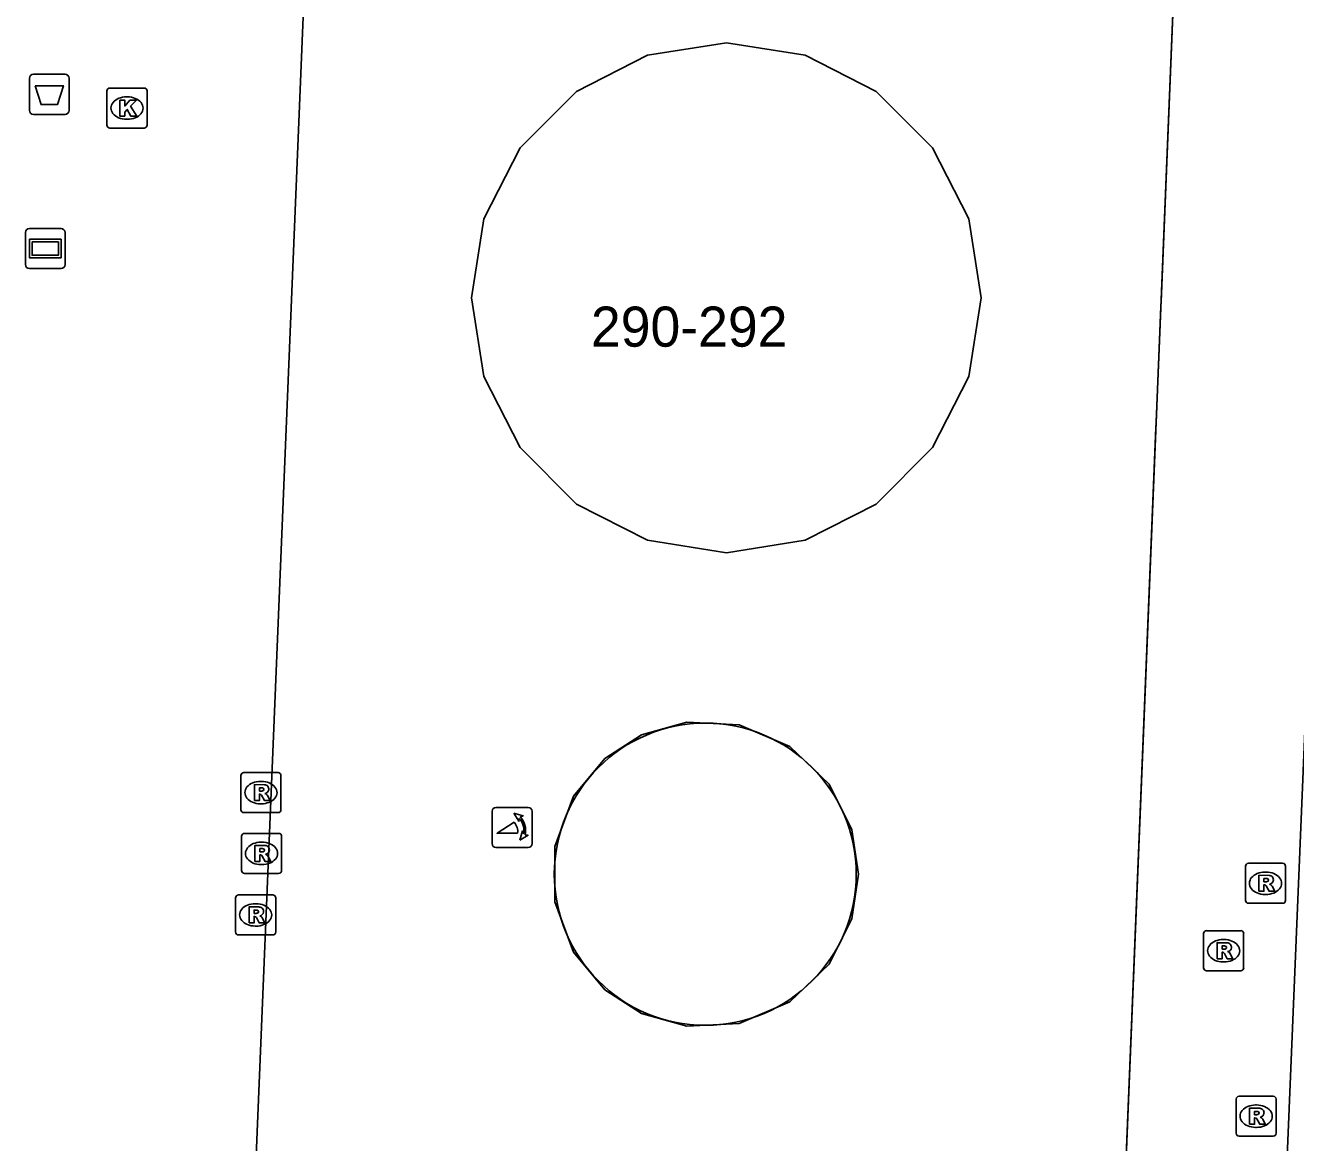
# Model space of a CAD drawing. Extents: x 160891 to 161384, y 386490 to 386907.
# Drawn here: x 161238.26 to 161269.97, y 386705.95 to 386733.83 of the extents above; entities that cross this region are included whole.
import ezdxf

# ---------------------------------------------------------------- set-up
doc = ezdxf.new("R2010")
doc.units = 0
for name, color, linetype in [('IMGEO_Afvalbak', 7, 'Continuous'), ('IMGEO_Kolk', 7, 'Continuous'), ('IMGEO_Pand', 7, 'Continuous'), ('IMGEO_Pand_nummerreeks', 7, 'Continuous'), ('IMGEO_Pand_overbouw', 7, 'Continuous'), ('IMGEO_Poller', 7, 'Continuous'), ('IMGEO_Reclamebord', 7, 'Continuous'), ('IMGEO_Rioolput', 7, 'Continuous'), ('IMGEO_Voetpad_open', 7, 'Continuous')]:
    doc.layers.add(name, color=color, linetype=linetype)

msp = doc.modelspace()

# ---------------------------------------------------------------- linework, layer by layer
at = {"layer": 'IMGEO_Afvalbak'}
for p, q in [((161238.358, 386731.708), (161238.358, 386732.508)), ((161238.358, 386732.508), (161238.358, 386731.708)), ((161238.458, 386732.608), (161239.248, 386732.608)), ((161239.248, 386732.608), (161238.458, 386732.608)), ((161239.348, 386732.508), (161239.348, 386731.708)), ((161239.348, 386731.708), (161239.348, 386732.508)), ((161239.248, 386731.608), (161238.458, 386731.608)), ((161238.458, 386731.608), (161239.248, 386731.608))]:
    msp.add_line(p, q, dxfattribs=at)
msp.add_lwpolyline([(161238.501, 386732.322), (161239.205, 386732.322), (161239.056, 386731.852), (161238.65, 386731.852), (161238.501, 386732.322)], dxfattribs=at)
for centre, start, end in [((161238.458, 386732.508), 90, 180), ((161238.458, 386732.508), 90, 180), ((161239.248, 386732.508), 0, 90), ((161239.248, 386732.508), 360, 90), ((161238.458, 386731.708), 180, 270), ((161238.458, 386731.708), 180, 270), ((161239.248, 386731.708), 270, 0), ((161239.248, 386731.708), 270, 0)]:
    msp.add_arc(centre, 0.1, start, end, dxfattribs=at)
at = {"layer": 'IMGEO_Kolk'}
for p, q in [((161240.293, 386731.339), (161240.293, 386732.191)), ((161240.368, 386732.265), (161241.22, 386732.265)), ((161241.294, 386732.191), (161241.294, 386731.339)), ((161240.781, 386732.045), (161240.806, 386732.045)), ((161241.22, 386731.265), (161240.368, 386731.265)), ((161240.804, 386731.485), (161240.779, 386731.485))]:
    msp.add_line(p, q, dxfattribs=at)
for points in [[(161240.293, 386731.339), (161240.293, 386732.191)], [(161240.368, 386732.265), (161241.22, 386732.265)], [(161241.294, 386732.191), (161241.294, 386731.339)], [(161240.614, 386731.965), (161240.737, 386731.965), (161240.737, 386731.814), (161240.867, 386731.965), (161241.031, 386731.965), (161240.885, 386731.814), (161241.038, 386731.565), (161240.886, 386731.565), (161240.801, 386731.729), (161240.737, 386731.662), (161240.737, 386731.565), (161240.614, 386731.565), (161240.614, 386731.965)], [(161241.22, 386731.265), (161240.368, 386731.265)]]:
    msp.add_lwpolyline(points, dxfattribs=at)
for centre, start, end in [((161240.37, 386732.189), 91.552, 178.448), ((161240.37, 386732.189), 91.552, 178.448), ((161241.218, 386732.189), 1.552, 88.448), ((161241.218, 386732.189), 1.552, 88.448), ((161240.37, 386731.341), 181.552, 268.448), ((161240.37, 386731.341), 181.552, 268.448), ((161241.218, 386731.341), 271.552, 358.448), ((161241.218, 386731.341), 271.552, 358.448)]:
    msp.add_arc(centre, 0.0765, start, end, dxfattribs=at)
for centre, major_axis, ratio, start_param, end_param in [((161240.78, 386731.765), (-0.387, 0.002), 0.722429, 4.712389, 7.853982), ((161240.805, 386731.765), (-0.39, 0.002), 0.717154, 1.570796, 4.712389)]:
    msp.add_ellipse(centre, major_axis=major_axis, ratio=ratio, start_param=start_param, end_param=end_param, dxfattribs=at)
at = {"layer": 'IMGEO_Pand'}
msp.add_lwpolyline([(161257.725, 386720.977), (161259.499, 386721.882), (161260.908, 386723.29), (161261.812, 386725.064), (161262.123, 386727.031), (161261.812, 386728.998), (161260.908, 386730.772), (161259.499, 386732.18), (161257.725, 386733.084), (161255.758, 386733.396), (161253.791, 386733.084), (161252.017, 386732.18), (161250.609, 386730.772), (161249.705, 386728.998), (161249.393, 386727.031), (161249.705, 386725.064), (161250.609, 386723.29), (161252.017, 386721.882), (161253.791, 386720.977), (161255.758, 386720.666), (161257.725, 386720.977)], dxfattribs=at)
at = {"layer": 'IMGEO_Pand_overbouw'}
for points in [[(161267.088, 386738.621), (161245.413, 386739.487), (161243.237, 386686.658), (161264.93, 386685.782)], [(161257.725, 386720.977), (161255.758, 386720.666), (161253.791, 386720.977), (161252.017, 386721.882), (161250.609, 386723.29), (161249.705, 386725.064), (161249.393, 386727.031), (161249.705, 386728.998), (161250.609, 386730.772), (161252.017, 386732.18), (161253.791, 386733.084), (161255.758, 386733.396), (161257.725, 386733.084), (161259.499, 386732.18), (161260.908, 386730.772), (161261.812, 386728.998), (161262.123, 386727.031), (161261.812, 386725.064), (161260.908, 386723.29), (161259.499, 386721.882)], [(161259.055, 386712.644), (161258.89, 386711.533), (161258.325, 386710.398), (161257.341, 386709.456), (161256.074, 386708.915), (161254.769, 386708.85), (161253.639, 386709.169), (161252.725, 386709.759), (161251.942, 386710.698), (161251.473, 386711.952), (161251.473, 386713.335), (161251.942, 386714.589), (161252.725, 386715.529), (161253.639, 386716.118), (161254.769, 386716.438), (161256.074, 386716.372), (161257.341, 386715.832), (161258.325, 386714.889), (161258.89, 386713.754)]]:
    msp.add_lwpolyline(points, close=True, dxfattribs=at)
at = {"layer": 'IMGEO_Poller'}
for p, q in [((161249.91, 386714.213), (161249.91, 386713.406)), ((161249.91, 386714.213), (161249.91, 386713.406)), ((161250.812, 386714.308), (161250.004, 386714.308)), ((161250.812, 386714.308), (161250.004, 386714.308)), ((161250.906, 386713.406), (161250.906, 386714.213)), ((161250.906, 386713.406), (161250.906, 386714.213)), ((161250.004, 386713.311), (161250.812, 386713.311)), ((161250.004, 386713.311), (161250.812, 386713.311))]:
    msp.add_line(p, q, dxfattribs=at)
for points in [[(161250.589, 386714.037), (161250.577, 386713.964), (161250.452, 386714.169)], [(161250.452, 386714.169), (161250.683, 386714.103), (161250.612, 386714.071)], [(161250.545, 386713.664), (161250.032, 386713.664), (161250.462, 386713.939)], [(161250.605, 386713.492), (161250.671, 386713.723), (161250.701, 386713.655)], [(161250.737, 386713.628), (161250.809, 386713.617), (161250.605, 386713.492)]]:
    msp.add_lwpolyline(points, dxfattribs=at)
for centre, radius, start, end in [((161250.004, 386714.213), 0.0946, 90, 180), ((161250.004, 386714.213), 0.0946, 90, 180), ((161250.812, 386714.213), 0.0946, 0, 90), ((161250.812, 386714.213), 0.0946, 0, 90), ((161250.217, 386713.714), 0.332, 351.3247, 42.4854), ((161250.231, 386713.724), 0.476, 351.7527, 41.1691), ((161250.231, 386713.724), 0.516, 349.3569, 42.2912), ((161250.004, 386713.406), 0.0946, 180, 270), ((161250.004, 386713.406), 0.0946, 180, 270), ((161250.812, 386713.406), 0.0946, 270, 0), ((161250.812, 386713.406), 0.0946, 270, 0)]:
    msp.add_arc(centre, radius, start, end, dxfattribs=at)
at = {"layer": 'IMGEO_Reclamebord'}
for p, q in [((161238.357, 386728.759), (161239.147, 386728.759)), ((161239.147, 386728.759), (161238.357, 386728.759)), ((161238.257, 386727.859), (161238.257, 386728.659)), ((161238.257, 386728.659), (161238.257, 386727.859)), ((161239.247, 386728.659), (161239.247, 386727.859)), ((161239.247, 386727.859), (161239.247, 386728.659)), ((161239.147, 386727.759), (161238.357, 386727.759)), ((161238.357, 386727.759), (161239.147, 386727.759))]:
    msp.add_line(p, q, dxfattribs=at)
for points in [[(161238.358, 386728.491), (161239.146, 386728.491), (161239.146, 386728.027), (161238.358, 386728.027), (161238.358, 386728.491)], [(161238.423, 386728.426), (161238.423, 386728.092), (161239.081, 386728.092), (161239.081, 386728.426), (161238.423, 386728.426)]]:
    msp.add_lwpolyline(points, dxfattribs=at)
for centre, start, end in [((161238.357, 386728.659), 90, 180), ((161238.357, 386728.659), 90, 180), ((161239.147, 386728.659), 0, 90), ((161239.147, 386728.659), 360, 90), ((161238.357, 386727.859), 180, 270), ((161238.357, 386727.859), 180, 270), ((161239.147, 386727.859), 270, 0), ((161239.147, 386727.859), 270, 0)]:
    msp.add_arc(centre, 0.1, start, end, dxfattribs=at)
at = {"layer": 'IMGEO_Rioolput'}
for p, q in [((161243.637, 386714.254), (161243.637, 386715.106)), ((161243.712, 386715.18), (161244.564, 386715.18)), ((161244.638, 386715.106), (161244.638, 386714.254)), ((161244.125, 386714.96), (161244.15, 386714.96)), ((161244.564, 386714.18), (161243.712, 386714.18)), ((161244.148, 386714.4), (161244.123, 386714.4)), ((161243.652, 386712.737), (161243.652, 386713.589)), ((161243.727, 386713.663), (161244.579, 386713.663)), ((161244.653, 386713.589), (161244.653, 386712.737)), ((161244.14, 386713.443), (161244.165, 386713.443)), ((161244.163, 386712.883), (161244.138, 386712.883)), ((161268.719, 386711.991), (161268.719, 386712.843)), ((161268.794, 386712.917), (161269.646, 386712.917)), ((161269.72, 386712.843), (161269.72, 386711.991)), ((161244.579, 386712.663), (161243.727, 386712.663)), ((161269.207, 386712.697), (161269.232, 386712.697)), ((161243.506, 386711.202), (161243.506, 386712.054)), ((161243.581, 386712.128), (161244.433, 386712.128)), ((161243.994, 386711.908), (161244.019, 386711.908)), ((161244.507, 386712.054), (161244.507, 386711.202)), ((161269.646, 386711.917), (161268.794, 386711.917)), ((161269.23, 386712.137), (161269.205, 386712.137)), ((161244.017, 386711.348), (161243.992, 386711.348)), ((161244.433, 386711.128), (161243.581, 386711.128)), ((161267.673, 386710.308), (161267.673, 386711.16)), ((161267.748, 386711.234), (161268.6, 386711.234)), ((161268.161, 386711.014), (161268.186, 386711.014)), ((161268.674, 386711.16), (161268.674, 386710.308)), ((161268.184, 386710.454), (161268.159, 386710.454)), ((161268.6, 386710.234), (161267.748, 386710.234)), ((161268.485, 386706.178), (161268.485, 386707.03)), ((161268.56, 386707.104), (161269.412, 386707.104)), ((161268.973, 386706.884), (161268.998, 386706.884)), ((161269.486, 386707.03), (161269.486, 386706.178)), ((161268.996, 386706.324), (161268.971, 386706.324)), ((161269.412, 386706.104), (161268.56, 386706.104))]:
    msp.add_line(p, q, dxfattribs=at)
for points in [[(161243.637, 386714.254), (161243.637, 386715.106)], [(161243.712, 386715.18), (161244.564, 386715.18)], [(161244.638, 386715.106), (161244.638, 386714.254)], [(161244.226, 386714.878), (161243.974, 386714.88), (161243.974, 386714.48)], [(161244.152, 386714.799), (161244.098, 386714.799), (161244.098, 386714.718)], [(161243.974, 386714.48), (161244.098, 386714.48), (161244.098, 386714.642), (161244.109, 386714.642)], [(161244.098, 386714.718), (161244.15, 386714.718)], [(161244.156, 386714.613), (161244.227, 386714.48), (161244.367, 386714.48), (161244.302, 386714.606)], [(161244.564, 386714.18), (161243.712, 386714.18)], [(161243.652, 386712.737), (161243.652, 386713.589)], [(161243.727, 386713.663), (161244.579, 386713.663)], [(161244.653, 386713.589), (161244.653, 386712.737)], [(161244.241, 386713.361), (161243.989, 386713.363), (161243.989, 386712.963)], [(161244.167, 386713.282), (161244.113, 386713.282), (161244.113, 386713.201)], [(161244.113, 386713.201), (161244.165, 386713.201)], [(161243.989, 386712.963), (161244.113, 386712.963), (161244.113, 386713.125), (161244.124, 386713.125)], [(161244.171, 386713.096), (161244.242, 386712.963), (161244.382, 386712.963), (161244.317, 386713.089)], [(161268.719, 386711.991), (161268.719, 386712.843)], [(161268.794, 386712.917), (161269.646, 386712.917)], [(161269.72, 386712.843), (161269.72, 386711.991)], [(161244.579, 386712.663), (161243.727, 386712.663)], [(161269.308, 386712.615), (161269.056, 386712.617), (161269.056, 386712.217)], [(161269.234, 386712.536), (161269.18, 386712.536), (161269.18, 386712.455)], [(161269.056, 386712.217), (161269.18, 386712.217), (161269.18, 386712.379), (161269.191, 386712.379)], [(161269.18, 386712.455), (161269.232, 386712.455)], [(161269.238, 386712.35), (161269.309, 386712.217), (161269.449, 386712.217), (161269.384, 386712.343)], [(161243.506, 386711.202), (161243.506, 386712.054)], [(161243.581, 386712.128), (161244.433, 386712.128)], [(161244.507, 386712.054), (161244.507, 386711.202)], [(161269.646, 386711.917), (161268.794, 386711.917)], [(161244.095, 386711.826), (161243.843, 386711.828), (161243.843, 386711.428)], [(161243.843, 386711.428), (161243.967, 386711.428), (161243.967, 386711.59), (161243.978, 386711.59)], [(161244.021, 386711.747), (161243.967, 386711.747), (161243.967, 386711.666)], [(161243.967, 386711.666), (161244.019, 386711.666)], [(161244.025, 386711.561), (161244.096, 386711.428), (161244.236, 386711.428), (161244.171, 386711.554)], [(161244.433, 386711.128), (161243.581, 386711.128)], [(161267.673, 386710.308), (161267.673, 386711.16)], [(161267.748, 386711.234), (161268.6, 386711.234)], [(161268.262, 386710.932), (161268.01, 386710.934), (161268.01, 386710.534)], [(161268.674, 386711.16), (161268.674, 386710.308)], [(161268.01, 386710.534), (161268.134, 386710.534), (161268.134, 386710.696), (161268.145, 386710.696)], [(161268.188, 386710.853), (161268.134, 386710.853), (161268.134, 386710.772)], [(161268.134, 386710.772), (161268.186, 386710.772)], [(161268.192, 386710.667), (161268.263, 386710.534), (161268.403, 386710.534), (161268.338, 386710.66)], [(161268.6, 386710.234), (161267.748, 386710.234)], [(161268.485, 386706.178), (161268.485, 386707.03)], [(161268.56, 386707.104), (161269.412, 386707.104)], [(161269.486, 386707.03), (161269.486, 386706.178)], [(161269.074, 386706.802), (161268.822, 386706.804), (161268.822, 386706.404)], [(161268.822, 386706.404), (161268.946, 386706.404), (161268.946, 386706.566), (161268.957, 386706.566)], [(161269, 386706.723), (161268.946, 386706.723), (161268.946, 386706.642)], [(161268.946, 386706.642), (161268.998, 386706.642)], [(161269.004, 386706.537), (161269.075, 386706.404), (161269.215, 386706.404), (161269.15, 386706.53)], [(161269.412, 386706.104), (161268.56, 386706.104)]]:
    msp.add_lwpolyline(points, dxfattribs=at)
for centre, radius, start, end in [((161243.714, 386715.104), 0.0765, 91.552, 178.448), ((161243.714, 386715.104), 0.0765, 91.552, 178.448), ((161244.562, 386715.104), 0.0765, 1.552, 88.448), ((161244.562, 386715.104), 0.0765, 1.552, 88.448), ((161244.158, 386714.703), 0.0964, 77.0061, 93.1865), ((161244.172, 386714.76), 0.0378, 276.6634, 79.6772), ((161244.225, 386714.768), 0.109, 350.3612, 89.416), ((161244.223, 386714.768), 0.112, 277.5842, 350.9817), ((161244.108, 386714.589), 0.0533, 26.0293, 88.6989), ((161244.134, 386714.907), 0.19, 274.7715, 282.9687), ((161244.207, 386714.553), 0.108, 29.5134, 73.7905), ((161243.714, 386714.256), 0.0765, 181.552, 268.448), ((161243.714, 386714.256), 0.0765, 181.552, 268.448), ((161244.562, 386714.256), 0.0765, 271.552, 358.448), ((161244.562, 386714.256), 0.0765, 271.552, 358.448), ((161243.729, 386713.587), 0.0765, 91.552, 178.448), ((161243.729, 386713.587), 0.0765, 91.552, 178.448), ((161244.577, 386713.587), 0.0765, 1.552, 88.448), ((161244.577, 386713.587), 0.0765, 1.552, 88.448), ((161244.149, 386713.39), 0.19, 274.7715, 282.9687), ((161244.173, 386713.186), 0.0964, 77.0061, 93.1865), ((161244.187, 386713.243), 0.0378, 276.6634, 79.6772), ((161244.24, 386713.251), 0.109, 350.3612, 89.416), ((161244.238, 386713.251), 0.112, 277.5842, 350.9817), ((161244.123, 386713.072), 0.0533, 26.0293, 88.6989), ((161244.222, 386713.036), 0.108, 29.5134, 73.7905), ((161268.796, 386712.841), 0.0765, 91.552, 178.448), ((161268.796, 386712.841), 0.0765, 91.552, 178.448), ((161269.644, 386712.841), 0.0765, 1.552, 88.448), ((161269.644, 386712.841), 0.0765, 1.552, 88.448), ((161243.729, 386712.739), 0.0765, 181.552, 268.448), ((161243.729, 386712.739), 0.0765, 181.552, 268.448), ((161244.577, 386712.739), 0.0765, 271.552, 358.448), ((161244.577, 386712.739), 0.0765, 271.552, 358.448), ((161269.24, 386712.44), 0.0964, 77.0061, 93.1865), ((161269.254, 386712.497), 0.0378, 276.6634, 79.6772), ((161269.307, 386712.505), 0.109, 350.3612, 89.416), ((161269.19, 386712.326), 0.0533, 26.0293, 88.6989), ((161269.216, 386712.644), 0.19, 274.7715, 282.9687), ((161269.305, 386712.505), 0.112, 277.5842, 350.9817), ((161269.289, 386712.29), 0.108, 29.5134, 73.7905), ((161243.583, 386712.052), 0.0765, 91.552, 178.448), ((161243.583, 386712.052), 0.0765, 91.552, 178.448), ((161244.431, 386712.052), 0.0765, 1.552, 88.448), ((161244.431, 386712.052), 0.0765, 1.552, 88.448), ((161268.796, 386711.993), 0.0765, 181.552, 268.448), ((161268.796, 386711.993), 0.0765, 181.552, 268.448), ((161269.644, 386711.993), 0.0765, 271.552, 358.448), ((161269.644, 386711.993), 0.0765, 271.552, 358.448), ((161243.977, 386711.537), 0.0533, 26.0293, 88.6989), ((161244.003, 386711.855), 0.19, 274.7715, 282.9687), ((161244.027, 386711.651), 0.0964, 77.0061, 93.1865), ((161244.041, 386711.708), 0.0378, 276.6634, 79.6772), ((161244.094, 386711.716), 0.109, 350.3612, 89.416), ((161244.092, 386711.716), 0.112, 277.5842, 350.9817), ((161244.076, 386711.501), 0.108, 29.5134, 73.7905), ((161243.583, 386711.204), 0.0765, 181.552, 268.448), ((161243.583, 386711.204), 0.0765, 181.552, 268.448), ((161244.431, 386711.204), 0.0765, 271.552, 358.448), ((161244.431, 386711.204), 0.0765, 271.552, 358.448), ((161267.75, 386711.158), 0.0765, 91.552, 178.448), ((161267.75, 386711.158), 0.0765, 91.552, 178.448), ((161268.261, 386710.822), 0.109, 350.3612, 89.416), ((161268.598, 386711.158), 0.0765, 1.552, 88.448), ((161268.598, 386711.158), 0.0765, 1.552, 88.448), ((161268.144, 386710.643), 0.0533, 26.0293, 88.6989), ((161268.17, 386710.961), 0.19, 274.7715, 282.9687), ((161268.194, 386710.757), 0.0964, 77.0061, 93.1865), ((161268.208, 386710.814), 0.0378, 276.6634, 79.6772), ((161268.259, 386710.822), 0.112, 277.5842, 350.9817), ((161268.243, 386710.607), 0.108, 29.5134, 73.7905), ((161267.75, 386710.31), 0.0765, 181.552, 268.448), ((161267.75, 386710.31), 0.0765, 181.552, 268.448), ((161268.598, 386710.31), 0.0765, 271.552, 358.448), ((161268.598, 386710.31), 0.0765, 271.552, 358.448), ((161268.562, 386707.028), 0.0765, 91.552, 178.448), ((161268.562, 386707.028), 0.0765, 91.552, 178.448), ((161269.41, 386707.028), 0.0765, 1.552, 88.448), ((161269.41, 386707.028), 0.0765, 1.552, 88.448), ((161268.956, 386706.513), 0.0533, 26.0293, 88.6989), ((161268.982, 386706.831), 0.19, 274.7715, 282.9687), ((161269.006, 386706.627), 0.0964, 77.0061, 93.1865), ((161269.02, 386706.684), 0.0378, 276.6634, 79.6772), ((161269.073, 386706.692), 0.109, 350.3612, 89.416), ((161269.071, 386706.692), 0.112, 277.5842, 350.9817), ((161269.055, 386706.477), 0.108, 29.5134, 73.7905), ((161268.562, 386706.18), 0.0765, 181.552, 268.448), ((161268.562, 386706.18), 0.0765, 181.552, 268.448), ((161269.41, 386706.18), 0.0765, 271.552, 358.448), ((161269.41, 386706.18), 0.0765, 271.552, 358.448)]:
    msp.add_arc(centre, radius, start, end, dxfattribs=at)
for centre, major_axis, ratio, start_param, end_param in [((161244.124, 386714.68), (-0.387, 0.002), 0.722429, 4.712389, 7.853982), ((161244.149, 386714.68), (-0.39, 0.002), 0.717154, 1.570796, 4.712389), ((161244.139, 386713.163), (-0.387, 0.002), 0.722429, 4.712389, 7.853982), ((161244.164, 386713.163), (-0.39, 0.002), 0.717154, 1.570796, 4.712389), ((161269.206, 386712.417), (-0.387, 0.002), 0.722429, 4.712389, 7.853982), ((161269.231, 386712.417), (-0.39, 0.002), 0.717154, 1.570796, 4.712389), ((161243.993, 386711.628), (-0.387, 0.002), 0.722429, 4.712389, 7.853982), ((161244.018, 386711.628), (-0.39, 0.002), 0.717154, 1.570796, 4.712389), ((161268.16, 386710.734), (-0.387, 0.002), 0.722429, 4.712389, 7.853982), ((161268.185, 386710.734), (-0.39, 0.002), 0.717154, 1.570796, 4.712389), ((161268.972, 386706.604), (-0.387, 0.002), 0.722429, 4.712389, 7.853982), ((161268.997, 386706.604), (-0.39, 0.002), 0.717154, 1.570796, 4.712389)]:
    msp.add_ellipse(centre, major_axis=major_axis, ratio=ratio, start_param=start_param, end_param=end_param, dxfattribs=at)
at = {"layer": 'IMGEO_Voetpad_open'}
for points in [[(161271.405, 386745.286), (161268.831, 386683.148)], [(161245.413, 386739.487), (161267.088, 386738.621), (161266.611, 386726.928), (161266.606, 386726.811), (161266.487, 386723.909), (161266.483, 386723.792), (161265.214, 386692.746), (161265.091, 386689.722), (161264.93, 386685.782), (161243.237, 386686.658), (161245.413, 386739.487)]]:
    msp.add_lwpolyline(points, dxfattribs=at)
for start, end in [(90, 270), (270, 90)]:
    msp.add_arc((161255.232, 386712.644), 3.77, start, end, dxfattribs=at)

# ---------------------------------------------------------------- texts
at = {"layer": 'IMGEO_Pand_nummerreeks'}
msp.add_text('290-292', height=1, dxfattribs=at).set_placement((161252.377, 386725.81))

doc.saveas('drawing.dxf')
